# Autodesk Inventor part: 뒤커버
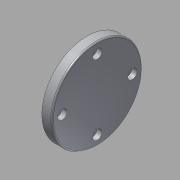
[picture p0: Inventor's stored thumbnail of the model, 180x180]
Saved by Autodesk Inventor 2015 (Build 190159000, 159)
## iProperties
Created: 2015-09
Part Number: 뒤커버
Material: 알루미늄 6061
Document SubType Name: Modeling
Designer: mduedu
Density: 2.71 g/cm^3
Mass: 54.0417 g
Surface Area: 84.9688 cm^2
Volume: 19.9416 cm^3
Appearance: 알루미늄 - 평지
Author: mduedu
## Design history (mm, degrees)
sketch "스케치1"
  geometry: L1 (-15.5, 47)-(-15.5, 78); L2 (-15.5, 78)-(-22.5, 78); L3 (-22.5, 78)-(-22.5, 67); L4 (-25.5, 67)-(-25.5, 47); L5 (-79.5, 39.5)-(-79.5, 54.5) reference; L6 (48.5, 54.5)-(48.5, 39.5) reference; L7 (-79.5, 47)-(48.5, 47); L8 (-22.5, 67)-(-25.5, 67); L9 (-25.5, 47)-(-15.5, 47); 1 further point
  constraints: 14 end point, 4 midpoint, 3 parallel, 1 collinear, 1 point on line, 1 vertical
  dimensions: "d6" = 62 diameter of L2 L7; "d7" = 7 distance of L1.end L2.end; "d8" = 40 diameter of L3.end L7; "d32" = 10 distance between parallel lines of L1 L4
revolve "회전1" sketch "스케치1" stored, may be unused: angle "d4" = 90 deg
sketch "스케치4"
  geometry: C1 r 31 at (0, 0) reference; 2 further points
  constraints: 1 coincident
hole "구멍3" sketch "스케치4" at (0, 0) diameter "d33" = 33; stored, may be unused: countersink angle "d37" = 90 deg, drill point angle "d39" = 0 deg; dims "d34" = 6, "d35" = 4, "d36" = 2, "d38" = 5
fillet "모깎기4" dims "d40" = 1
chamfer "모따기2" distance "d41" = 1; stored, may be unused: second distance "d42" = 2, angle "d43" = 45 deg
sketch "스케치5" dims "d44" = 48
  geometry: C1 r 31 at (0, 0) reference; 6 further points
  constraints: 2 vertical alignment, 1 coincident, 7 other
  dimensions: "d47" = 360 deg dimension on C1.centre point (0, -24) (derived)
sketch "스케치6"
  geometry: 4 further points
hole "구멍4" sketch "스케치6" at (24, 0), (0, 24), (-24, 0), (0, -24) diameter "d49" = 3.4; stored, may be unused: countersink angle "d53" = 90 deg, drill point angle "d55" = 0 deg; dims "d50" = 6, "d51" = 6.5, "d52" = 3.4, "d54" = 8
node "솔리드1"
node "참조1"
node "참조2"
